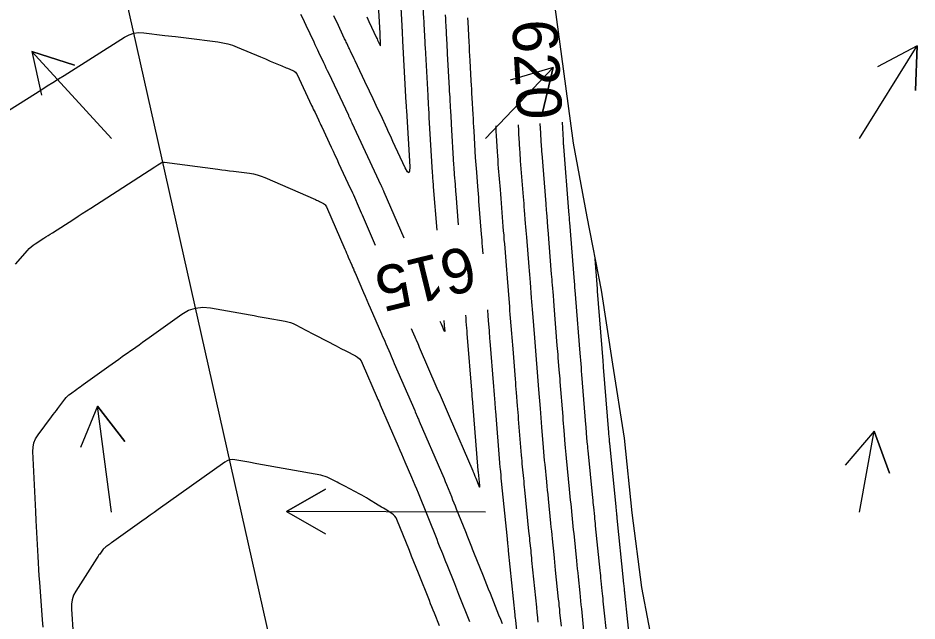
# Model space of a CAD drawing. Extents: x 954385 to 988206, y 1868364 to 1924553.
# Drawn here: x 958094.6 to 958214.8, y 1918454.4 to 1918535.1 of the extents above; entities that cross this region are included whole.
import ezdxf

# ---------------------------------------------------------------- set-up
doc = ezdxf.new("R2010")
doc.units = 0
for name, color, linetype in [('24', 7, 'Continuous'), ('26', 7, 'Continuous'), ('5', 7, 'Continuous'), ('6', 7, 'Continuous'), ('7', 7, 'Continuous'), ('Default', 7, 'Continuous')]:
    doc.layers.add(name, color=color, linetype=linetype)

msp = doc.modelspace()

# ---------------------------------------------------------------- linework, layer by layer
at = {"layer": '24'}
msp.add_lwpolyline([(958166.17, 1918538.23), (958167.51, 1918528.28), (958168.87, 1918518.33), (958170.66, 1918508.49), (958172.59, 1918498.67), (958174.13, 1918488.77), (958175.69, 1918478.87), (958176.71, 1918468.85), (958177.97, 1918458.88), (958179.86, 1918449.06), (958179.87, 1918447.9), (958182.32, 1918439.36), (958183.91, 1918429.47), (958185.71, 1918419.63), (958187.13, 1918409.7), (958188.43, 1918399.74), (958190.03, 1918389.85), (958192.01, 1918380.04), (958194.13, 1918370.27), (958196.15, 1918360.48), (958197.73, 1918350.58), (958199.86, 1918340.81)], dxfattribs=at)
at = {"layer": '26'}
for points in [[(958107.13, 1918518.93), (958096.45, 1918530.59), (958102.17, 1918528.78), (958096.45, 1918530.59), (958097.75, 1918524.73)], [(958207.13, 1918518.93), (958214.83, 1918531.36), (958214.64, 1918525.36), (958214.83, 1918531.36), (958209.54, 1918528.52)], [(958157.13, 1918518.93), (958166.17, 1918528.45), (958164.77, 1918522.61), (958166.17, 1918528.45), (958160.42, 1918526.74)], [(958107.13, 1918468.93), (958105.24, 1918483.14), (958108.9, 1918478.39), (958105.24, 1918483.14), (958102.95, 1918477.59)], [(958207.13, 1918468.93), (958209.11, 1918479.8), (958211.13, 1918474.15), (958209.11, 1918479.8), (958205.23, 1918475.22)], [(958157.13, 1918468.93), (958130.52, 1918469.06), (958135.74, 1918472.04), (958130.52, 1918469.06), (958135.71, 1918466.04)]]:
    msp.add_lwpolyline(points, dxfattribs=at)
at = {"layer": '6'}
for points in [[(958148.53, 1918540.54), (958148.84, 1918534.99), (958148.86, 1918534.67), (958148.87, 1918534.34), (958148.89, 1918534.02), (958148.91, 1918533.7), (958148.98, 1918532.42), (958149, 1918532.1), (958149.02, 1918531.78), (958149.03, 1918531.45), (958149.05, 1918531.13), (958149.4, 1918524.71), (958149.41, 1918524.46), (958149.43, 1918524.22), (958149.44, 1918523.97), (958149.45, 1918523.73), (958149.51, 1918522.75), (958149.53, 1918522.51), (958149.54, 1918522.27), (958149.55, 1918522.02), (958149.57, 1918521.78), (958150, 1918514.42), (958150.01, 1918514.26), (958150.02, 1918514.1), (958150.03, 1918513.94), (958150.04, 1918513.78), (958150.09, 1918513.14), (958150.12, 1918512.82), (958150.14, 1918512.49), (958150.6, 1918506.7)], [(958146.24, 1918505.63), (958143.59, 1918511.75), (958143.52, 1918511.9), (958143.41, 1918512.16), (958143.38, 1918512.24), (958143.34, 1918512.32), (958143.27, 1918512.49), (958143.25, 1918512.54), (958143.23, 1918512.58), (958143.21, 1918512.62), (958143.19, 1918512.66), (958139.3, 1918521.01), (958139.22, 1918521.18), (958139.15, 1918521.35), (958138.99, 1918521.69), (958138.95, 1918521.77), (958138.91, 1918521.86), (958138.87, 1918521.94), (958138.83, 1918522.03), (958136.16, 1918527.68), (958136, 1918528.02), (958135.83, 1918528.37), (958135.67, 1918528.71), (958135.51, 1918529.06), (958134.86, 1918530.44), (958134.7, 1918530.78), (958134.53, 1918531.13), (958134.37, 1918531.47), (958134.21, 1918531.82), (958133.14, 1918534.08), (958132.91, 1918534.57), (958132.68, 1918535.07), (958132.44, 1918535.56)], [(958170.29, 1918453.08), (958169.99, 1918456), (958169.93, 1918456.53), (958169.88, 1918457.07), (958169.82, 1918457.6), (958169.77, 1918458.14), (958169.55, 1918460.29), (958169.5, 1918460.82), (958169.44, 1918461.36), (958169.39, 1918461.89), (958169.33, 1918462.43), (958168.96, 1918466.1), (958168.91, 1918466.59), (958168.86, 1918467.09), (958168.81, 1918467.58), (958168.76, 1918468.08), (958168.56, 1918470.06), (958168.51, 1918470.56), (958168.46, 1918471.05), (958168.41, 1918471.55), (958168.36, 1918472.05), (958167.95, 1918476.18), (958167.91, 1918476.65), (958167.86, 1918477.11), (958167.82, 1918477.58), (958167.78, 1918478.04), (958167.64, 1918479.9), (958167.6, 1918480.37), (958167.56, 1918480.83), (958167.52, 1918481.3), (958167.49, 1918481.76), (958167.12, 1918486.37), (958167.09, 1918486.77), (958167.06, 1918487.18), (958167.02, 1918487.59), (958166.99, 1918488), (958166.86, 1918489.63), (958166.83, 1918490.03), (958166.8, 1918490.44), (958166.76, 1918490.85), (958166.73, 1918491.25), (958166.31, 1918496.54), (958166.25, 1918497.25), (958166.2, 1918497.96), (958166.09, 1918499.38), (958166.06, 1918499.73), (958166.03, 1918500.09), (958166, 1918500.44), (958165.97, 1918500.8), (958165.5, 1918506.74), (958165.47, 1918507.03), (958165.45, 1918507.32), (958165.43, 1918507.61), (958165.41, 1918507.89), (958165.31, 1918509.05), (958165.29, 1918509.33), (958165.27, 1918509.62), (958165.25, 1918509.91), (958165.22, 1918510.2), (958164.69, 1918516.93), (958164.67, 1918517.16), (958164.65, 1918517.39), (958164.64, 1918517.61), (958164.62, 1918517.84), (958164.57, 1918518.76), (958164.56, 1918518.99), (958164.54, 1918519.21), (958164.53, 1918519.44), (958164.52, 1918519.67), (958164.44, 1918520.97)], [(958151.57, 1918494.58), (958151.62, 1918493.96), (958151.62, 1918493.89), (958151.68, 1918493.23), (958151.68, 1918493.15), (958151.67, 1918493.12), (958151.64, 1918493.14), (958151.61, 1918493.21), (958151.36, 1918493.78), (958151.22, 1918494.12), (958151.07, 1918494.46)]]:
    msp.add_lwpolyline(points, dxfattribs=at)
at = {"layer": '7'}
for points in [[(958145.53, 1918541.36), (958145.93, 1918534.02), (958145.94, 1918533.86), (958145.95, 1918533.69), (958145.96, 1918533.52), (958145.97, 1918533.35), (958146, 1918532.68), (958146.01, 1918532.51), (958146.02, 1918532.34), (958146.03, 1918532.17), (958146.04, 1918532.01), (958146.49, 1918523.73), (958146.49, 1918523.65), (958146.5, 1918523.56), (958146.5, 1918523.48), (958146.51, 1918523.39), (958146.53, 1918522.96), (958146.54, 1918522.79), (958146.55, 1918522.71), (958146.99, 1918515.18), (958146.98, 1918514.57), (958146.89, 1918514.34), (958146.69, 1918514.49), (958146.4, 1918515.03), (958144.75, 1918518.57), (958144.56, 1918518.98), (958144.36, 1918519.4), (958144.17, 1918519.82), (958143.97, 1918520.23), (958143.11, 1918522.1), (958142.96, 1918522.42), (958142.81, 1918522.73), (958142.66, 1918523.05), (958142.51, 1918523.37), (958141.91, 1918524.64), (958141.76, 1918524.96), (958141.61, 1918525.28), (958141.46, 1918525.6), (958141.31, 1918525.91), (958139.69, 1918529.34), (958139.56, 1918529.63), (958139.42, 1918529.92), (958139.14, 1918530.51), (958139.07, 1918530.65), (958139, 1918530.8), (958138.93, 1918530.95), (958138.87, 1918531.09), (958138.58, 1918531.7), (958138.51, 1918531.85), (958138.44, 1918532), (958138.37, 1918532.15), (958138.29, 1918532.3), (958137.24, 1918534.55), (958137.04, 1918534.96), (958136.85, 1918535.37)], [(958141.24, 1918535.21), (958141.38, 1918534.91), (958141.51, 1918534.62), (958142.55, 1918532.42), (958142.63, 1918532.27), (958142.7, 1918532.11), (958143, 1918531.48), (958143.05, 1918531.39), (958143.08, 1918531.36), (958143.1, 1918531.4), (958143.1, 1918531.51), (958143.03, 1918532.89), (958143.02, 1918533.06), (958142.52, 1918542.18)], [(958153.53, 1918507.42), (958153.2, 1918511.53), (958153.17, 1918511.85), (958153.15, 1918512.18), (958153.12, 1918512.5), (958153.1, 1918512.82), (958152.99, 1918514.11), (958152.97, 1918514.44), (958152.94, 1918514.76), (958152.92, 1918515.08), (958152.9, 1918515.41), (958152.59, 1918520.85), (958152.56, 1918521.25), (958152.54, 1918521.66), (958152.52, 1918522.06), (958152.49, 1918522.46), (958152.4, 1918524.07), (958152.38, 1918524.47), (958152.35, 1918524.88), (958152.33, 1918525.28), (958152.31, 1918525.68), (958152.06, 1918530.26), (958152.03, 1918530.73), (958152.01, 1918531.21), (958151.98, 1918531.68), (958151.96, 1918532.16), (958151.85, 1918534.05), (958151.83, 1918534.53), (958151.8, 1918535), (958151.78, 1918535.48)], [(958156.82, 1918503.5), (958156.74, 1918504.52), (958156.7, 1918504.94), (958156.67, 1918505.35), (958156.64, 1918505.76), (958156.6, 1918506.17), (958156.25, 1918510.57), (958156.22, 1918511.05), (958156.18, 1918511.54), (958156.14, 1918512.02), (958156.1, 1918512.51), (958155.95, 1918514.45), (958155.91, 1918514.93), (958155.87, 1918515.42), (958155.84, 1918515.9), (958155.81, 1918516.39), (958155.61, 1918519.92), (958155.57, 1918520.49), (958155.54, 1918521.05), (958155.51, 1918521.61), (958155.48, 1918522.17), (958155.35, 1918524.41), (958155.31, 1918524.97), (958155.28, 1918525.53), (958155.25, 1918526.09), (958155.22, 1918526.65), (958155.07, 1918529.39), (958155.04, 1918530.02), (958155, 1918530.64), (958154.97, 1918531.27), (958154.93, 1918531.9), (958154.79, 1918534.5), (958154.76, 1918535.08)], [(958092.48, 1918522.16), (958097.78, 1918525.51), (958098.53, 1918525.99), (958099.27, 1918526.46), (958100.02, 1918526.93), (958100.77, 1918527.4), (958108.84, 1918532.52), (958109.46, 1918532.84), (958110.09, 1918533.04), (958110.76, 1918533.13), (958111.45, 1918533.1), (958114.26, 1918532.75), (958115.67, 1918532.58), (958117.08, 1918532.41), (958121.34, 1918531.88), (958122.01, 1918531.77), (958122.67, 1918531.62), (958123.31, 1918531.43), (958123.94, 1918531.18), (958127.06, 1918529.86), (958127.7, 1918529.59), (958128.34, 1918529.32), (958129.91, 1918528.66), (958130.09, 1918528.58), (958130.28, 1918528.5), (958130.46, 1918528.42), (958130.64, 1918528.35), (958131.38, 1918528.03), (958131.55, 1918527.94), (958131.7, 1918527.83), (958131.82, 1918527.69), (958131.92, 1918527.52), (958133.87, 1918523.37), (958133.99, 1918523.13), (958134.1, 1918522.89), (958134.21, 1918522.66), (958134.33, 1918522.42), (958134.78, 1918521.46), (958134.89, 1918521.22), (958135, 1918520.98), (958135.11, 1918520.74), (958135.23, 1918520.5), (958136.49, 1918517.8), (958136.74, 1918517.27), (958136.98, 1918516.74), (958137.23, 1918516.21), (958137.48, 1918515.67), (958139.05, 1918512.29), (958139.19, 1918512), (958139.32, 1918511.7), (958139.46, 1918511.41), (958139.59, 1918511.11), (958140.1, 1918509.92), (958140.23, 1918509.62), (958140.36, 1918509.32), (958140.49, 1918509.02), (958140.62, 1918508.72), (958142.37, 1918504.68)], [(958161.49, 1918520.8), (958161.5, 1918520.6), (958161.52, 1918520.21), (958161.54, 1918519.83), (958161.56, 1918519.44), (958161.59, 1918519.05), (958161.68, 1918517.5), (958161.7, 1918517.12), (958161.73, 1918516.73), (958161.75, 1918516.34), (958161.78, 1918515.96), (958162.17, 1918511.16), (958162.2, 1918510.71), (958162.24, 1918510.26), (958162.27, 1918509.81), (958162.31, 1918509.36), (958162.45, 1918507.56), (958162.49, 1918507.11), (958162.52, 1918506.66), (958162.56, 1918506.21), (958162.6, 1918505.76), (958162.91, 1918501.78), (958162.96, 1918501.26), (958163, 1918500.74), (958163.04, 1918500.22), (958163.08, 1918499.7), (958163.24, 1918497.63), (958163.29, 1918497.11), (958163.33, 1918496.59), (958163.37, 1918496.07), (958163.41, 1918495.56), (958163.67, 1918492.29), (958163.72, 1918491.71), (958163.76, 1918491.13), (958163.81, 1918490.56), (958163.85, 1918489.98), (958164.04, 1918487.68), (958164.08, 1918487.1), (958164.13, 1918486.52), (958164.18, 1918485.95), (958164.22, 1918485.37), (958164.43, 1918482.8), (958164.47, 1918482.18), (958164.52, 1918481.56), (958164.57, 1918480.94), (958164.62, 1918480.32), (958164.84, 1918477.6), (958164.89, 1918477.03), (958164.94, 1918476.46), (958164.99, 1918475.88), (958165.05, 1918475.31), (958165.27, 1918473.02), (958165.33, 1918472.45), (958165.39, 1918471.88), (958165.45, 1918471.3), (958165.5, 1918470.73), (958165.83, 1918467.48), (958165.88, 1918466.95), (958165.93, 1918466.43), (958165.99, 1918465.91), (958166.04, 1918465.39), (958166.25, 1918463.3), (958166.3, 1918462.78), (958166.36, 1918462.25), (958166.41, 1918461.73), (958166.46, 1918461.21), (958166.86, 1918457.31), (958166.91, 1918456.86), (958166.95, 1918456.41), (958167, 1918455.96), (958167.04, 1918455.51), (958167.23, 1918453.7)], [(958173.42, 1918451.77), (958172.88, 1918457.04), (958172.84, 1918457.38), (958172.81, 1918457.72), (958172.77, 1918458.07), (958172.74, 1918458.41), (958172.6, 1918459.78), (958172.56, 1918460.12), (958172.53, 1918460.46), (958172.49, 1918460.8), (958172.46, 1918461.15), (958171.85, 1918467.12), (958171.82, 1918467.43), (958171.79, 1918467.74), (958171.76, 1918468.06), (958171.73, 1918468.37), (958171.6, 1918469.61), (958171.57, 1918469.92), (958171.54, 1918470.23), (958171.51, 1918470.54), (958171.48, 1918470.85), (958170.84, 1918477.19), (958170.82, 1918477.48), (958170.79, 1918477.77), (958170.76, 1918478.06), (958170.74, 1918478.35), (958170.65, 1918479.52), (958170.62, 1918479.81), (958170.6, 1918480.1), (958170.58, 1918480.39), (958170.55, 1918480.68), (958170.02, 1918487.36), (958169.98, 1918487.84), (958169.95, 1918488.31), (958169.87, 1918489.27), (958169.83, 1918489.75), (958169.79, 1918490.22), (958169.21, 1918497.52), (958169.17, 1918498.1), (958169.09, 1918499.05), (958169.06, 1918499.43), (958169.03, 1918499.82), (958168.4, 1918507.72), (958168.38, 1918507.97), (958168.36, 1918508.23), (958168.31, 1918508.86), (958168.29, 1918509.11), (958168.28, 1918509.23), (958167.59, 1918517.9), (958167.58, 1918517.97), (958167.58, 1918518.04), (958167.57, 1918518.11), (958167.57, 1918518.18), (958167.55, 1918518.53), (958167.54, 1918518.74), (958167.4, 1918521.13)], [(958164.18, 1918454.23), (958164.08, 1918455.24), (958164.05, 1918455.5), (958164.02, 1918455.75), (958164, 1918456.01), (958163.97, 1918456.26), (958163.34, 1918462.49), (958163.31, 1918462.82), (958163.27, 1918463.15), (958163.24, 1918463.48), (958163.21, 1918463.8), (958163.07, 1918465.12), (958163.04, 1918465.45), (958163.01, 1918465.77), (958162.97, 1918466.1), (958162.94, 1918466.43), (958162.39, 1918471.92), (958162.35, 1918472.31), (958162.31, 1918472.7), (958162.28, 1918473.09), (958162.24, 1918473.47), (958162.08, 1918475.02), (958162.04, 1918475.41), (958162.01, 1918475.8), (958161.97, 1918476.19), (958161.94, 1918476.57), (958161.56, 1918481.4), (958161.52, 1918481.85), (958161.49, 1918482.3), (958161.45, 1918482.74), (958161.42, 1918483.19), (958161.27, 1918484.97), (958161.24, 1918485.42), (958161.2, 1918485.87), (958161.17, 1918486.31), (958161.13, 1918486.76), (958160.81, 1918490.8), (958160.77, 1918491.31), (958160.73, 1918491.83), (958160.69, 1918492.34), (958160.65, 1918492.85), (958160.48, 1918494.91), (958160.44, 1918495.42), (958160.4, 1918495.94), (958160.36, 1918496.45), (958160.32, 1918496.96), (958160.06, 1918500.24), (958160.01, 1918500.82), (958159.97, 1918501.39), (958159.92, 1918501.97), (958159.87, 1918502.55), (958159.69, 1918504.85), (958159.64, 1918505.43), (958159.6, 1918506), (958159.55, 1918506.58), (958159.51, 1918507.16), (958159.31, 1918509.68), (958159.26, 1918510.29), (958159.21, 1918510.9), (958159.16, 1918511.51), (958159.11, 1918512.12), (958158.88, 1918514.98), (958158.84, 1918515.53), (958158.8, 1918516.07), (958158.77, 1918516.62), (958158.73, 1918517.16), (958158.6, 1918519.34), (958158.57, 1918519.89), (958158.54, 1918520.44), (958158.53, 1918520.64)], [(958094.28, 1918502.13), (958095.88, 1918503.98), (958096.11, 1918504.22), (958096.36, 1918504.46), (958096.63, 1918504.67), (958096.91, 1918504.86), (958098.06, 1918505.6), (958098.35, 1918505.79), (958098.64, 1918505.97), (958098.93, 1918506.16), (958099.22, 1918506.34), (958102.07, 1918508.17), (958102.64, 1918508.54), (958103.21, 1918508.9), (958103.78, 1918509.27), (958104.35, 1918509.64), (958112.91, 1918515.14), (958113.33, 1918515.41), (958113.75, 1918515.68), (958113.86, 1918515.73), (958113.97, 1918515.77), (958114.09, 1918515.78), (958114.21, 1918515.78), (958121.32, 1918514.85), (958121.85, 1918514.78), (958122.38, 1918514.71), (958122.91, 1918514.64), (958123.44, 1918514.57), (958125.57, 1918514.3), (958126.09, 1918514.21), (958126.61, 1918514.08), (958127.12, 1918513.93), (958127.61, 1918513.73), (958134.39, 1918510.78), (958134.53, 1918510.72), (958134.66, 1918510.65), (958134.8, 1918510.59), (958134.93, 1918510.52), (958135.47, 1918510.24), (958135.6, 1918510.16), (958135.7, 1918510.07), (958135.79, 1918509.95), (958135.86, 1918509.82), (958138.32, 1918504.14), (958138.44, 1918503.87), (958138.55, 1918503.61), (958138.67, 1918503.34), (958138.78, 1918503.08), (958139.24, 1918502.02), (958139.35, 1918501.75), (958139.47, 1918501.49), (958139.58, 1918501.22), (958139.7, 1918500.96), (958140.82, 1918498.36), (958141.04, 1918497.84), (958141.27, 1918497.32), (958141.49, 1918496.8), (958141.72, 1918496.28), (958143.22, 1918492.8), (958143.36, 1918492.47), (958143.51, 1918492.14), (958143.65, 1918491.82), (958143.79, 1918491.49), (958144.36, 1918490.17), (958144.5, 1918489.84), (958144.65, 1918489.51), (958144.79, 1918489.18), (958144.93, 1918488.85), (958147.66, 1918482.54), (958147.73, 1918482.37), (958148.04, 1918481.67), (958148.09, 1918481.53), (958148.15, 1918481.4), (958148.21, 1918481.27), (958148.26, 1918481.14), (958151.24, 1918474.26), (958151.41, 1918473.86), (958151.58, 1918473.46), (958151.75, 1918473.05), (958151.91, 1918472.65), (958152.56, 1918471.03), (958152.73, 1918470.62), (958152.89, 1918470.22), (958153.05, 1918469.81), (958153.21, 1918469.41), (958154.44, 1918466.35), (958154.53, 1918466.12), (958154.62, 1918465.89), (958154.72, 1918465.66), (958154.81, 1918465.43), (958155.18, 1918464.52), (958155.27, 1918464.29), (958155.36, 1918464.06), (958155.45, 1918463.83), (958155.54, 1918463.6), (958156.81, 1918460.42), (958157.04, 1918459.84), (958157.27, 1918459.27), (958157.5, 1918458.69), (958157.73, 1918458.11), (958158.65, 1918455.81), (958158.88, 1918455.23), (958159.11, 1918454.65), (958159.34, 1918454.07)], [(958176.55, 1918450.45), (958175.76, 1918458.09), (958175.75, 1918458.23), (958175.73, 1918458.38), (958175.72, 1918458.53), (958175.7, 1918458.68), (958175.63, 1918459.42), (958175.6, 1918459.71), (958175.58, 1918459.86), (958174.74, 1918468.15), (958174.73, 1918468.28), (958174.71, 1918468.4), (958174.7, 1918468.53), (958174.69, 1918468.65), (958174.63, 1918469.28), (958174.6, 1918469.54), (958174.59, 1918469.66), (958173.74, 1918478.19), (958173.72, 1918478.31), (958173.71, 1918478.43), (958173.7, 1918478.54), (958173.69, 1918478.66), (958173.66, 1918479.13), (958173.64, 1918479.37), (958173.62, 1918479.6), (958172.92, 1918488.35), (958172.9, 1918488.63), (958172.87, 1918489.05), (958172.86, 1918489.19), (958172.11, 1918498.54), (958172.09, 1918498.83), (958171.77, 1918502.87)], [(958097.97, 1918453.56), (958097.89, 1918454.56), (958097.51, 1918459.57), (958097.45, 1918460.43), (958097.39, 1918461.3), (958097.34, 1918462.16), (958097.29, 1918463.03), (958097.06, 1918467.82), (958097, 1918469.02), (958096.6, 1918477.06), (958096.62, 1918477.67), (958096.74, 1918478.24), (958096.96, 1918478.78), (958097.29, 1918479.3), (958099.11, 1918481.72), (958099.32, 1918482), (958099.53, 1918482.28), (958099.74, 1918482.55), (958099.95, 1918482.83), (958100.88, 1918484.08), (958101.05, 1918484.28), (958101.23, 1918484.47), (958101.42, 1918484.64), (958101.63, 1918484.8), (958102.49, 1918485.42), (958102.7, 1918485.57), (958102.91, 1918485.72), (958103.13, 1918485.88), (958103.34, 1918486.03), (958106.76, 1918488.47), (958107.2, 1918488.79), (958107.65, 1918489.11), (958108.1, 1918489.44), (958108.55, 1918489.76), (958110.35, 1918491.04), (958110.8, 1918491.36), (958111.25, 1918491.68), (958111.69, 1918492), (958112.14, 1918492.32), (958116.5, 1918495.43), (958117.4, 1918495.96), (958118.34, 1918496.27), (958119.33, 1918496.39), (958120.37, 1918496.3), (958125.64, 1918495.35), (958126.18, 1918495.25), (958126.73, 1918495.15), (958127.27, 1918495.06), (958127.81, 1918494.96), (958130.32, 1918494.51), (958130.69, 1918494.42), (958131.05, 1918494.32), (958131.4, 1918494.18), (958131.75, 1918494.02), (958133.1, 1918493.31), (958133.44, 1918493.13), (958133.78, 1918492.96), (958134.12, 1918492.78), (958134.46, 1918492.6), (958137.16, 1918491.2), (958137.8, 1918490.86), (958138.44, 1918490.53), (958139.72, 1918489.87), (958140.01, 1918489.68), (958140.27, 1918489.45), (958140.48, 1918489.18), (958140.64, 1918488.87), (958142.63, 1918484.26), (958142.73, 1918484.03), (958142.84, 1918483.79), (958142.94, 1918483.56), (958143.04, 1918483.33), (958145.43, 1918477.78), (958145.66, 1918477.26), (958145.88, 1918476.74), (958146.11, 1918476.22), (958146.33, 1918475.7), (958147.23, 1918473.62), (958147.46, 1918473.1), (958147.68, 1918472.58), (958147.89, 1918472.06), (958148.1, 1918471.53), (958150.6, 1918465.32), (958150.77, 1918464.89), (958150.94, 1918464.46), (958151.36, 1918463.42), (958151.41, 1918463.3), (958151.46, 1918463.18), (958151.5, 1918463.06), (958151.55, 1918462.94), (958151.79, 1918462.34), (958151.94, 1918461.97), (958152.96, 1918459.4), (958153.11, 1918459.04), (958153.25, 1918458.69), (958153.39, 1918458.34), (958153.53, 1918457.98), (958155, 1918454.3)], [(958161.67, 1918449.48), (958161.16, 1918454.52), (958161.13, 1918454.75), (958161.11, 1918454.98), (958161.1, 1918455.1), (958161.09, 1918455.21), (958160.22, 1918463.78), (958160.19, 1918464.04), (958160.16, 1918464.31), (958160.11, 1918464.85), (958160.09, 1918464.98), (958160.08, 1918465.12), (958160.07, 1918465.25), (958160.05, 1918465.39), (958159.28, 1918473.11), (958159.24, 1918473.52), (958159.2, 1918473.93), (958159.12, 1918474.74), (958159.1, 1918474.94), (958159.08, 1918475.14), (958159.06, 1918475.34), (958159.04, 1918475.55), (958158.49, 1918482.48), (958158.47, 1918482.75), (958158.45, 1918483.03), (958158.43, 1918483.3), (958158.4, 1918483.57), (958158.32, 1918484.66), (958158.27, 1918485.21), (958158.23, 1918485.76), (958157.75, 1918491.83), (958157.72, 1918492.17), (958157.69, 1918492.52), (958157.67, 1918492.86), (958157.64, 1918493.21), (958157.53, 1918494.59), (958157.47, 1918495.28), (958157.42, 1918495.97), (958157.41, 1918496.02)], [(958147.2, 1918493.51), (958147.32, 1918493.22), (958147.5, 1918492.82), (958147.67, 1918492.41), (958147.76, 1918492.21), (958147.85, 1918492.01), (958148.06, 1918491.52), (958148.16, 1918491.29), (958148.26, 1918491.05), (958150.64, 1918485.54), (958151.05, 1918484.61), (958151.45, 1918483.68), (958151.85, 1918482.74), (958152.26, 1918481.81), (958155.42, 1918474.5), (958155.45, 1918474.42), (958155.49, 1918474.34), (958155.52, 1918474.25), (958155.55, 1918474.17), (958155.72, 1918473.75), (958155.82, 1918473.5), (958156.23, 1918472.48), (958156.3, 1918472.34), (958156.34, 1918472.29), (958156.36, 1918472.35), (958156.35, 1918472.51), (958156.17, 1918474.32), (958156.15, 1918474.45), (958156.15, 1918474.47), (958156.15, 1918474.48), (958156.15, 1918474.5), (958156.15, 1918474.52), (958155.43, 1918483.56), (958155.41, 1918483.76), (958155.39, 1918483.96), (958155.35, 1918484.55), (958155.33, 1918484.75), (958154.69, 1918492.86), (958154.66, 1918493.21), (958154.63, 1918493.56), (958154.56, 1918494.45), (958154.52, 1918494.97), (958154.49, 1918495.3)], [(958150.97, 1918453.74), (958150.3, 1918455.43), (958150.13, 1918455.85), (958149.96, 1918456.27), (958149.79, 1918456.7), (958149.62, 1918457.12), (958148.16, 1918460.8), (958147.86, 1918461.55), (958147.55, 1918462.31), (958147.25, 1918463.06), (958146.95, 1918463.81), (958145.28, 1918467.96), (958145.17, 1918468.2), (958145.02, 1918468.41), (958144.84, 1918468.6), (958144.62, 1918468.75), (958143.7, 1918469.33), (958143.47, 1918469.47), (958143.24, 1918469.61), (958143.01, 1918469.75), (958142.78, 1918469.9), (958141.49, 1918470.7), (958141.2, 1918470.88), (958140.91, 1918471.05), (958140.61, 1918471.22), (958140.3, 1918471.38), (958138.32, 1918472.41), (958138.06, 1918472.55), (958137.79, 1918472.69), (958137.53, 1918472.83), (958137.27, 1918472.96), (958136.22, 1918473.51), (958135.95, 1918473.64), (958135.67, 1918473.74), (958135.39, 1918473.83), (958135.11, 1918473.89), (958126.57, 1918475.43), (958125.46, 1918475.63), (958123.61, 1918475.96), (958123.25, 1918476), (958122.9, 1918475.95), (958122.57, 1918475.84), (958122.26, 1918475.66), (958113.36, 1918469.31), (958112.82, 1918468.92), (958112.27, 1918468.53), (958111.73, 1918468.14), (958111.18, 1918467.75), (958107.13, 1918464.86), (958107.03, 1918464.79), (958106.93, 1918464.72), (958106.83, 1918464.65), (958106.74, 1918464.58), (958106.35, 1918464.3), (958106.25, 1918464.23), (958106.17, 1918464.15), (958106.09, 1918464.07), (958106.01, 1918463.98), (958105.54, 1918463.35), (958105.44, 1918463.22), (958105.34, 1918463.08), (958105.25, 1918462.94), (958105.16, 1918462.8), (958102.35, 1918458.39), (958102.05, 1918457.83), (958101.85, 1918457.24), (958101.75, 1918456.63), (958101.75, 1918455.99), (958102.01, 1918452.58)]]:
    msp.add_lwpolyline(points, dxfattribs=at)
at = {"layer": 'Default'}
msp.add_line((958200.6, 1918129.72), (957843.86, 1919719.4), dxfattribs=at)

# ---------------------------------------------------------------- texts
at = {"layer": '5'}
for s, rotation, p in [('620', 273.2068, (958160.67, 1918534.71)), ('615', 193.7765, (958154.94, 1918504.68))]:
    msp.add_text(s, height=6, rotation=rotation, dxfattribs=at).set_placement(p)

doc.saveas('drawing.dxf')
